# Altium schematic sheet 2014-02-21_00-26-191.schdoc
size 449 x 172 mm; SheetNumber: 1; SheetTotal: 1
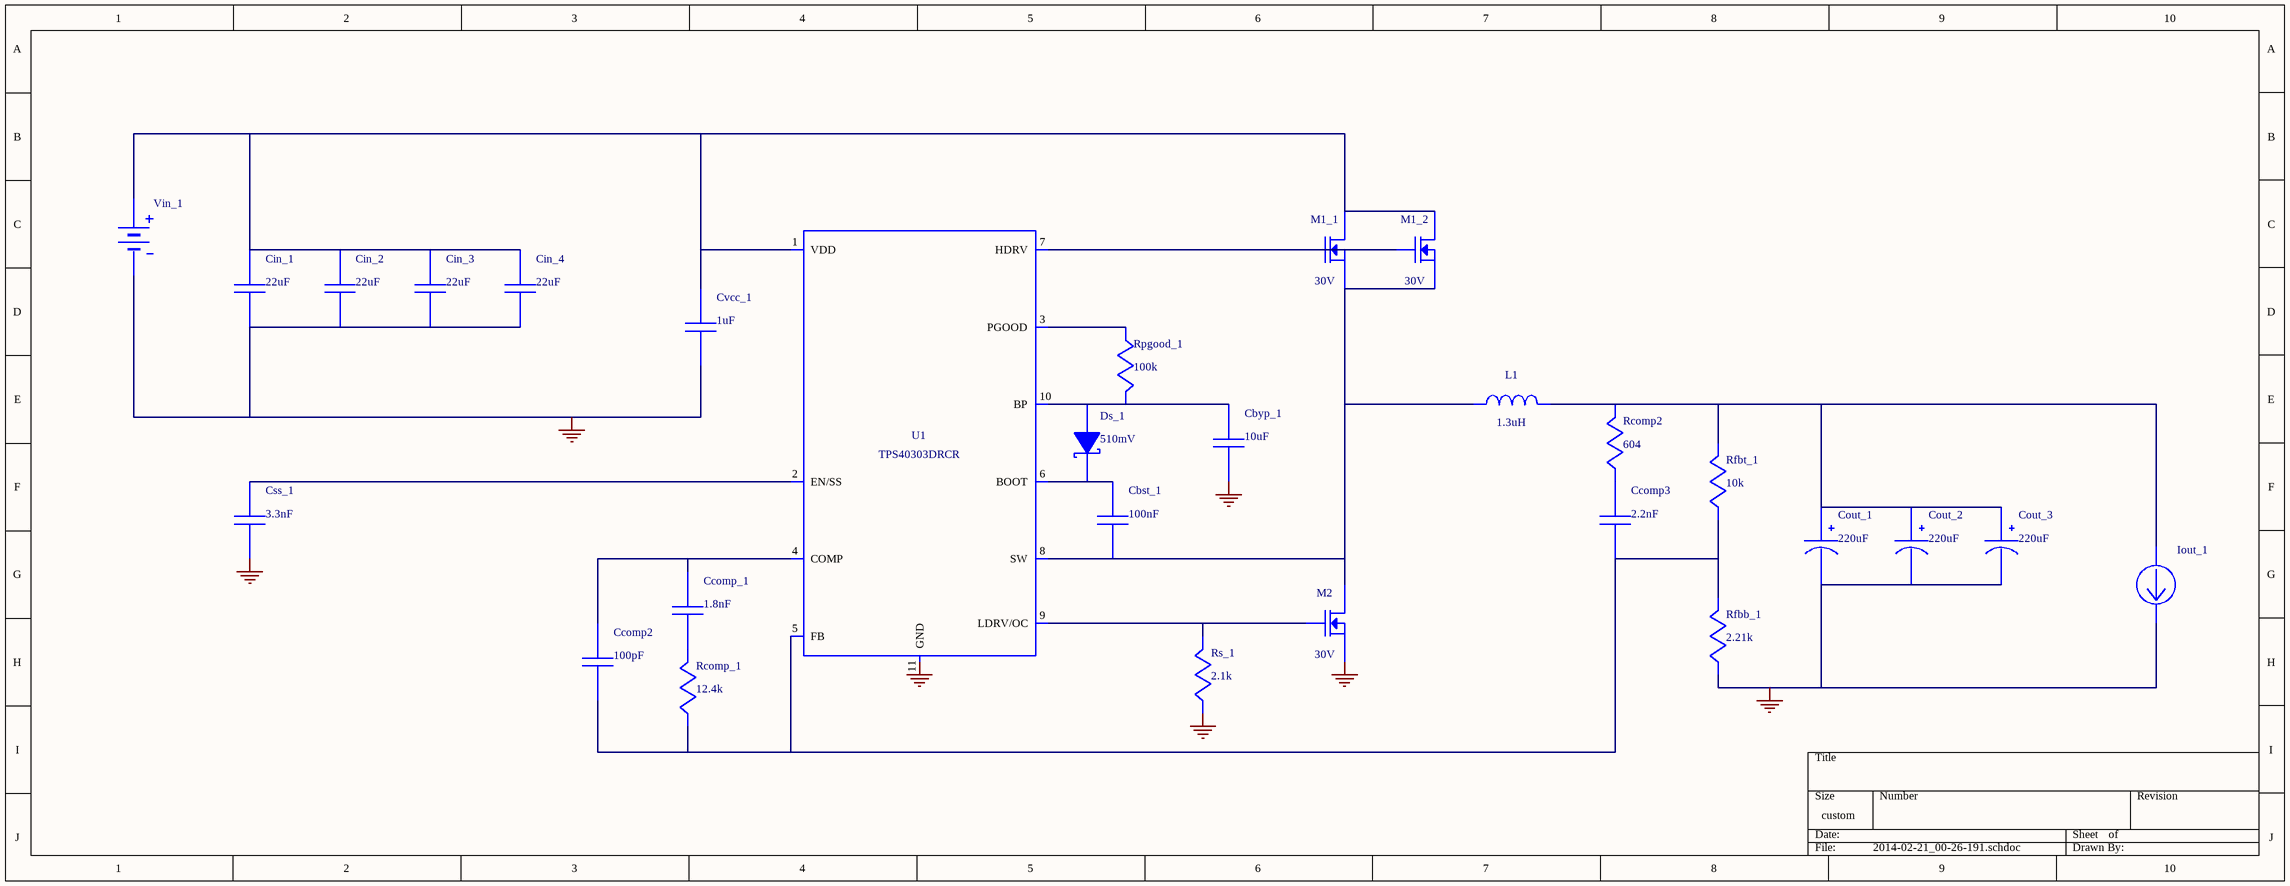
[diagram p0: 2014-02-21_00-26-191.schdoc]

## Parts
Cbst_1  value 100nF  (hidden comment: 08053C104KAT2A)
Cbyp_1  value 10uF  (hidden comment: GRM21BR61A106KE19L)
Ccomp2  value 100pF  (hidden comment: CC0805JRNP09BN101)
Ccomp3  value 2.2nF  (hidden comment: CC0805KRX7R9BB222)
Ccomp_1  value 1.8nF  (hidden comment: GRM155R71H182KA01D)
Cin_1  value 22uF  (hidden comment: GRM32ER61E226KE15L)
Cin_2  value 22uF  (hidden comment: GRM32ER61E226KE15L)
Cin_3  value 22uF  (hidden comment: GRM32ER61E226KE15L)
Cin_4  value 22uF  (hidden comment: GRM32ER61E226KE15L)
Cout_1  value 220uF  (hidden comment: T520D227M006ATE009)
Cout_2  value 220uF  (hidden comment: T520D227M006ATE009)
Cout_3  value 220uF  (hidden comment: T520D227M006ATE009)
Css_1  value 3.3nF  (hidden comment: GRM033R71C332KA88D)
Cvcc_1  value 1uF  (hidden comment: GRM188R61E105KA12D)
Ds_1  value 510mV  (hidden comment: MBR0540T1G)
Iout_1  WB_CURRENT_LOAD  (value not drawn)
L1  value 1.3uH  (hidden comment: XAL1580-132MEB)
M1_1  value 30V  (hidden comment: CSD17311Q5)
M1_2  value 30V  (hidden comment: CSD17311Q5)
M2  value 30V  (hidden comment: CSD17311Q5)
Rcomp2  value 604  (hidden comment: CRCW0402604RFKED)
Rcomp_1  value 12.4k  (hidden comment: CRCW040212K4FKED)
Rfbb_1  value 2.21k  (hidden comment: CRCW04022K21FKED)
Rfbt_1  value 10k  (hidden comment: CRCW040210K0FKED)
Rpgood_1  value 100k  (hidden comment: CRCW0402100KFKED)
Rs_1  value 2.1k  (hidden comment: CRCW04022K10FKED)
U1  TPS40303DRCR
Vin_1  WB_BATTERY  (value not drawn)

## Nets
0: Cbyp_1.2 Cin_1.2 Cin_2.2 Cin_3.2 Cin_4.2 Cout_1.2(-) Cout_2.2(-) Cout_3.2(-) Css_1.2 Cvcc_1.2 Iout_1.2(-) M2.1(Source) M2.2(Source) M2.3(Source) Rfbb_1.2 Rs_1.2 Vin_1.2(-)
NetCbst_1_1: Cbst_1.1 Ds_1.1(K) U1.6(BOOT)
NetCbst_1_2: Cbst_1.2 L1.2 M1_1.1(Source) M1_1.2(Source) M1_1.3(Source) M1_2.1(Source) M1_2.2(Source) M1_2.3(Source) M2.5(Drain) M2.6(Drain) M2.7(Drain) M2.8(Drain) U1.8(SW)
NetCbyp_1_1: Cbyp_1.1 Ds_1.2(A) Rpgood_1.1 U1.10(BP)
NetCcomp2_1: Ccomp2.1 Ccomp3.2 Rcomp_1.2 Rfbb_1.1 Rfbt_1.2 U1.5(FB)
NetCcomp2_2: Ccomp2.2 Ccomp_1.2 U1.4(COMP)
NetCcomp3_1: Ccomp3.1 Rcomp2.2
NetCcomp_1_1: Ccomp_1.1 Rcomp_1.1
NetCin_1_1: Cin_1.1 Cin_2.1 Cin_3.1 Cin_4.1 Cvcc_1.1 M1_1.5(Drain) M1_1.6(Drain) M1_1.7(Drain) M1_1.8(Drain) M1_2.5(Drain) M1_2.6(Drain) M1_2.7(Drain) M1_2.8(Drain) U1.1(VDD) Vin_1.1(+)
NetCout_1_1: Cout_1.1(+) Cout_2.1(+) Cout_3.1(+) Iout_1.1(+) L1.1 Rcomp2.1 Rfbt_1.1
NetCss_1_1: Css_1.1 U1.2(EN/SS)
NetM1_1_4: M1_1.4(Gate) M1_2.4(Gate) U1.7(HDRV)
NetM2_4: M2.4(Gate) Rs_1.1 U1.9(LDRV/OC)
NetRpgood_1_2: Rpgood_1.2 U1.3(PGOOD)

Not connected (* = marked no-connect by the designer): U1 11(GND)

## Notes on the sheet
- Labels drawn without touching a wire or pin: 0

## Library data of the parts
Cbst_1 = 08053C104KAT2A: Manufacturer Name: AVX
Cbyp_1 = GRM21BR61A106KE19L: GRM21BR61A106KE1; Manufacturer Name: MuRata
Ccomp2 = CC0805JRNP09BN101: CC0805JRNP09BN10; Manufacturer Name: Yageo America
Ccomp3 = CC0805KRX7R9BB222: CC0805KRX7R9BB22; Manufacturer Name: Yageo America
Ccomp_1 = GRM155R71H182KA01D: GRM155R71H182KA0; Manufacturer Name: MuRata
Cin_1-Cin_4 = GRM32ER61E226KE15L: GRM32ER61E226KE1; Manufacturer Name: MuRata
Cout_1-Cout_3 = T520D227M006ATE009: T520D227M006ATE0; Manufacturer Name: Kemet
Css_1 = GRM033R71C332KA88D: GRM033R71C332KA8; Manufacturer Name: MuRata
Cvcc_1 = GRM188R61E105KA12D: GRM188R61E105KA1; Manufacturer Name: MuRata
Ds_1 = MBR0540T1G: Manufacturer Name: ON Semiconductor
Iout_1 = WB_CURRENT_LOAD: Value: UNLISTED
L1 = XAL1580-132MEB: Manufacturer Name: Coilcraft
M1_1 M1_2 M2 = CSD17311Q5: Manufacturer Name: Texas Instruments
Rcomp2 = CRCW0402604RFKED: Manufacturer Name: Vishay-Dale
Rcomp_1 = CRCW040212K4FKED: Manufacturer Name: Vishay-Dale
Rfbb_1 = CRCW04022K21FKED: Manufacturer Name: Vishay-Dale
Rfbt_1 = CRCW040210K0FKED: Manufacturer Name: Vishay-Dale
Rpgood_1 = CRCW0402100KFKED: Manufacturer Name: Vishay-Dale
Rs_1 = CRCW04022K10FKED: Manufacturer Name: Vishay-Dale
U1 = TPS40303DRCR: Manufacturer Name: Texas Instruments; Value: UNLISTED
Vin_1 = WB_BATTERY: Value: UNLISTED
